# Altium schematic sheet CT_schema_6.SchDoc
size 277 x 170 mm
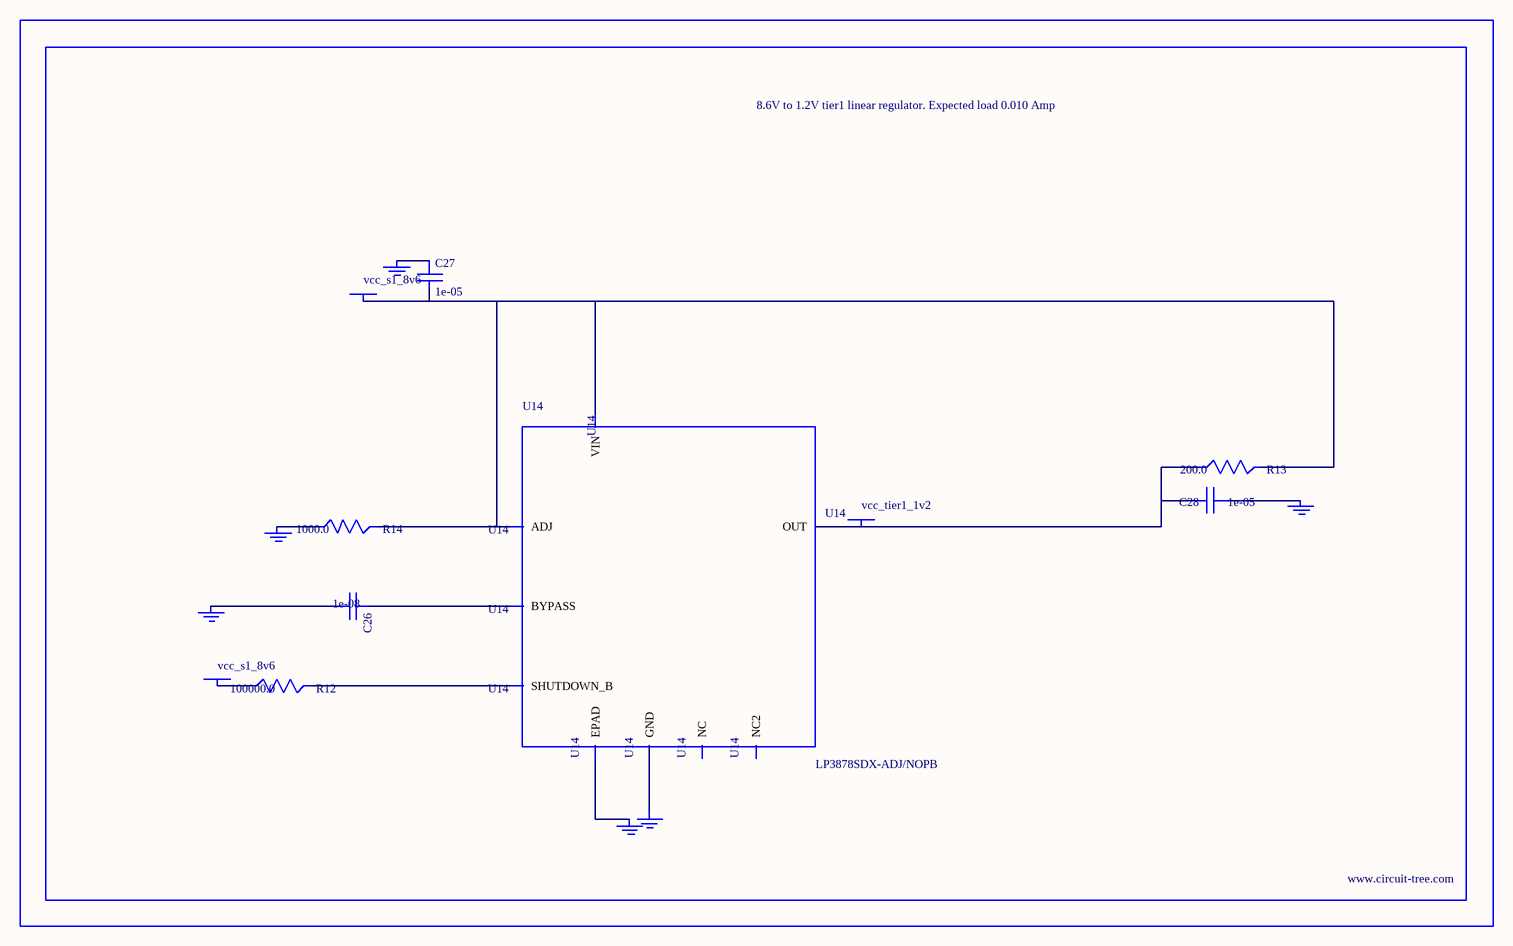
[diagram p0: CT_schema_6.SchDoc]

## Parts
BORDER5  (no value)
C26  1e-08  [C0402]
C27  1e-05  [C1206]
C28  1e-05  [C0805]
GND_INSTANCE_5_0  (no value)
GND_INSTANCE_5_1  (no value)
GND_INSTANCE_5_2  (no value)
GND_INSTANCE_5_3  (no value)
GND_INSTANCE_5_4  (no value)
GND_INSTANCE_5_5  (no value)
POWER_INSTANCE_5_0  vcc_s1_8v6
POWER_INSTANCE_5_1  vcc_s1_8v6
POWER_INSTANCE_5_2  vcc_tier1_1v2
R12  100000.0  [R0603]
R13  200.0  [R0603]
R14  1000.0  [R0603]
U14  LP3878SDX-ADJ/NOPB  [WSON-8]

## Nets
NetC26_1: C26.1 U14.1(BYPASS)
NetC26_2: C26.2 GND_INSTANCE_5_0.0(GND)
NetC27_1: C27.1 GND_INSTANCE_5_1.0(GND)
NetC27_2: C27.2 POWER_INSTANCE_5_0.0(PWR) R13.2 R14.2 U14.4(VIN) U14.6(ADJ)
NetC28_1: C28.1 GND_INSTANCE_5_2.0(GND)
NetC28_2: C28.2 POWER_INSTANCE_5_2.0(PWR) R13.1 U14.5(OUT)
NetGND_INSTANCE_5_3_0: GND_INSTANCE_5_3.0(GND) R14.1
NetGND_INSTANCE_5_4_0: GND_INSTANCE_5_4.0(GND) U14.PAD(EPAD)
NetGND_INSTANCE_5_5_0: GND_INSTANCE_5_5.0(GND) U14.3(GND)
NetPOWER_INSTANCE_5_1_0: POWER_INSTANCE_5_1.0(PWR) R12.1
NetR12_2: R12.2 U14.8(SHUTDOWN_B)

Not connected (* = marked no-connect by the designer): U14 2(NC) 7(NC2)

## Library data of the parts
BORDER5 = BORDER_PAGE5
C26 = C0402C103K3RAC
C27 = C1206C106K3RACTU
C28 = GRM219R60J106ME19D
GND_INSTANCE_5_0-GND_INSTANCE_5_5 = GND
POWER_INSTANCE_5_0-POWER_INSTANCE_5_2 = PWR
R12 = RC0603JR-07100KL
R13 = RC0603JR-07200RL
R14 = RC0603JR-071KL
